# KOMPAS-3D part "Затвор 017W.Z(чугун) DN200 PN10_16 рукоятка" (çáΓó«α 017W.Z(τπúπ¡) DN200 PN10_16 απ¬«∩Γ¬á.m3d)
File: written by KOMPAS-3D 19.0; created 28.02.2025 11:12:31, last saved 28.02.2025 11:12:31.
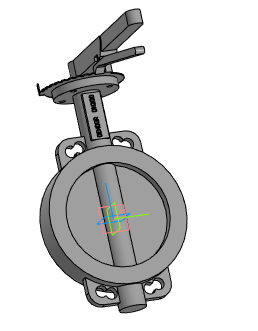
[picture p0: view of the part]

Document properties: Автор: Евгений; Полное имя файла: Затвор 017W.Z(чугун) DN200 PN10_16 рукоятка.a3d

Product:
- Part/product: Затвор 017W.Z(чугун) DN200 PN10_16 рукоятка
    Масса: 26.4147

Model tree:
1. Операция без истории:1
